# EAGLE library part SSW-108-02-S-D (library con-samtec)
THROUGH-HOLE .025" SQ POST SOCKET Source: Samtec SSW.pdf
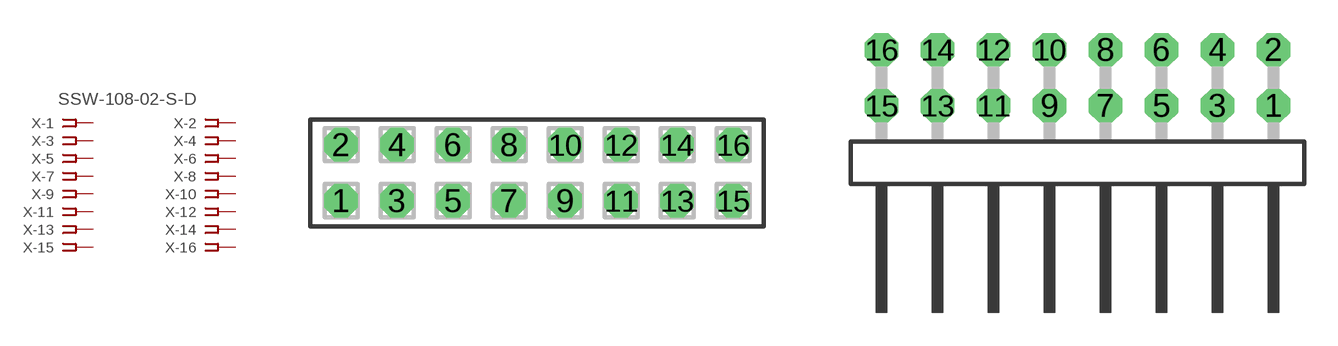
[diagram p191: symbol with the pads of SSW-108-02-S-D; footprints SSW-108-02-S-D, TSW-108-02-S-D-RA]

Designator prefix X; gates -1=FPINV -2=FPIN -3=FPIN -4=FPIN -5=FPIN -6=FPIN -7=FPIN -8=FPIN -9=FPIN -10=FPIN -11=FPIN -12=FPIN -13=FPIN -14=FPIN -15=FPIN -16=FPIN

## SSW-108-02-S-D (MPN: SSW-108-02-S-D; OC_FARNELL: unknown; OC_NEWARK: 85K7646)  [SSW-108-02-S-D]
1  -1:1  pas
2  -2:1  pas
3  -3:1  pas
4  -4:1  pas
5  -5:1  pas
6  -6:1  pas
7  -7:1  pas
8  -8:1  pas
9  -9:1  pas
10  -10:1  pas
11  -11:1  pas
12  -12:1  pas
13  -13:1  pas
14  -14:1  pas
15  -15:1  pas
16  -16:1  pas

## SSW-108-02-S-D-RA (MPN: SSW-108-02-S-D-RA; OC_FARNELL: unknown; OC_NEWARK: 11P9447)  [TSW-108-02-S-D-RA]
Pads as for SSW-108-02-S-D

## Footprint SSW-108-02-S-D (pad centres in mm)
THROUGH-HOLE .025" SQ POST SOCKET Source: Samtec SSW.pdf
drill 1 pad 1.5 octagon: 1 -8.89,-1.27; 2 -8.89,1.27; 3 -6.35,-1.27; 4 -6.35,1.27; 5 -3.81,-1.27; 6 -3.81,1.27; 7 -1.27,-1.27; 8 -1.27,1.27; 9 1.27,-1.27; 10 1.27,1.27; 11 3.81,-1.27; 12 3.81,1.27; 13 6.35,-1.27; 14 6.35,1.27; 15 8.89,-1.27; 16 8.89,1.27

## Footprint TSW-108-02-S-D-RA (pad centres in mm)
THROUGH-HOLE .025" SQ POST HEADER Source: Samtec TSW.pdf
drill 1 pad 1.5 octagon: 1 8.89,1.524; 2 8.89,4.064; 3 6.35,1.524; 4 6.35,4.064; 5 3.81,1.524; 6 3.81,4.064; 7 1.27,1.524; 8 1.27,4.064; 9 -1.27,1.524; 10 -1.27,4.064; 11 -3.81,1.524; 12 -3.81,4.064; 13 -6.35,1.524; 14 -6.35,4.064; 15 -8.89,1.524; 16 -8.89,4.064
